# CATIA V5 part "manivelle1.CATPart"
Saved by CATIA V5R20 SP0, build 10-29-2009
Part number: manivelle
Bounding box of the stored display mesh (mm): x 0 to 5, y -9.765 to 111.179, z -85.032 to 13.107
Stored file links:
  C:\Users\thinkmotion1\Desktop\IAO OK\IAO_2010_1458_splanchena\Correction_Khaled\manivelle1.CATPart
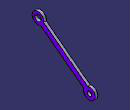
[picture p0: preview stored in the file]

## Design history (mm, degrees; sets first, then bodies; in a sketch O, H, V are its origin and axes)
Body1 (main body)
  Sketch1 on yz-plane, origin (0, 0, 0), H (0, 1, 0), V (0, 0, 1)
    arc A1 centre (1.2341, 2.1133) radius 11 from (12.0675, 0.2061) to (6.0343, -7.7841) ccw
    circle A2 centre (1.2341, 2.1133) radius 6
    arc A3 centre (100.1878, -74.032) radius 11 from (89.6393, -70.9126) to (96.6099, -63.6301) ccw
    circle A4 centre (100.1878, -74.032) radius 4.25
    point P3 (12.0292, 0)
    line L1 (6.0343, -7.7841) -> (89.6393, -70.9126)
    line L2 (12.0675, 0.2061) -> (96.6099, -63.6301)
    radius A2 = 6
    radius A1 = 11
    radius A3 = 11
    radius A4 = 4.25
    angle L2 L1 = 0
    coincidence: P3 A1, P3 H
  Pad1: profile Sketch1, direction (1, 0, 0), length 5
